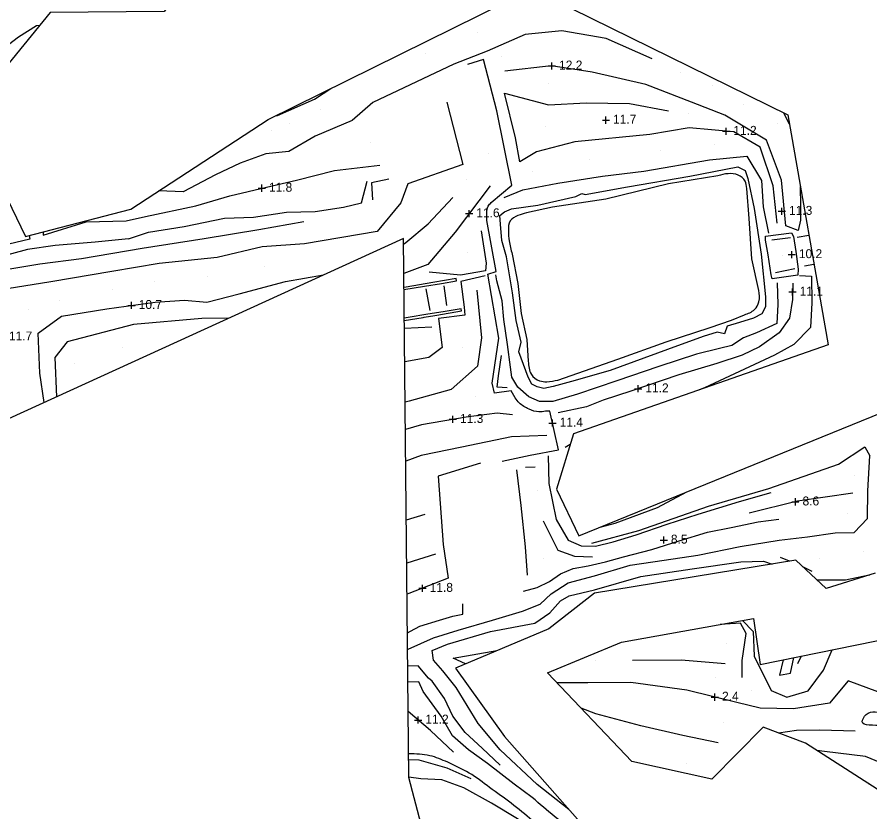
# Model space of a CAD drawing. Extents: x 2316231 to 2323598, y 363169 to 371906.
# Drawn here: x 2320880.2 to 2321357, y 369532.1 to 369976.5 of the extents above; entities that cross this region are included whole.
import ezdxf

# ---------------------------------------------------------------- set-up
doc = ezdxf.new("R2010")
doc.units = 0
for name, color, linetype in [('RD_DTM_BkLn1', 7, 'Continuous'), ('RD_DTM_Holes', 7, 'Continuous'), ('RD_DTM_Spot', 7, 'Continuous'), ('RD_DTM_TinHull', 7, 'Continuous'), ('RD_DTM_Void', 7, 'Continuous'), ('RD_EX_BldgApp', 7, 'Continuous'), ('RD_EX_H2O', 7, 'Continuous'), ('RD_EX_Road', 7, 'Continuous')]:
    doc.layers.add(name, color=color, linetype=linetype)

msp = doc.modelspace()

# ---------------------------------------------------------------- linework, layer by layer
at = {"layer": 'RD_DTM_BkLn1'}
for p, q in [((2321308.763, 369922.978), (2321311.938, 369916.742)), ((2321312.663, 369853.017), (2321302.145, 369851.663)), ((2321322.916, 369854.266), (2321316.329, 369853.314)), ((2321315.13, 369835.66), (2321304.272, 369833.408)), ((2321325.758, 369838.09), (2321320.399, 369837.22)), ((2321120.499, 369815.164), (2321119.001, 369826.233)), ((2321111.166, 369812.365), (2321109.01, 369824.539)), ((2321112.054, 369803.166), (2321096.729, 369802.277)), ((2321189.428, 369737.419), (2321186.709, 369735.907)), ((2321169.929, 369724.893), (2321164.543, 369724.581)), ((2321108.152, 369698.325), (2321097.812, 369695.229)), ((2321114.104, 369676.116), (2321098.056, 369671.125)), ((2321312.118, 369672.265), (2321306.975, 369674.295)), ((2321324.665, 369666.464), (2321319.862, 369668.929)), ((2321318.571, 369619.232), (2321316.569, 369614.883)), ((2321356.472, 369547.716), (2321356.759, 369547.802))]:
    msp.add_line(p, q, dxfattribs=at)
for points in [[(2320892.805, 369971.78), (2320891.11, 369971.664), (2320881.063, 369965.204), (2320869.634, 369956.682)], [(2321235.278, 369953.103), (2321209.567, 369964.402), (2321184.688, 369968.693), (2321164.253, 369966.7), (2321143.04, 369957.439), (2321124.355, 369950.144), (2321079.106, 369928.678), (2321067.49, 369918.696), (2321046.854, 369909.915), (2321032.108, 369901.364), (2321019.376, 369899.987), (2321004.974, 369894.795), (2320991.093, 369888.286), (2320972.982, 369878.763), (2320959.429, 369879.291)], [(2321318.087, 369881.749), (2321318.258, 369870.999), (2321318.219, 369862.984), (2321316.921, 369857.224), (2321310.009, 369859.798), (2321307.636, 369885.215), (2321299.19, 369907.738), (2321275.988, 369921.576), (2321257.216, 369928.974), (2321231.814, 369938.855), (2321201.776, 369945.722), (2321178.793, 369949.206), (2321152.99, 369946.161)], [(2321025.194, 369921.484), (2321025.821, 369921.483), (2321046.504, 369930.646), (2321055.7, 369936.567)], [(2321305.137, 369861.226), (2321302.843, 369882.113), (2321295.687, 369903.821), (2321280.9, 369912.222), (2321256.056, 369914.523), (2321234.016, 369910.864), (2321192.066, 369906.66), (2321170.523, 369901.133), (2321161.278, 369895.512), (2321158.825, 369908.935), (2321152.729, 369933.853), (2321177.316, 369927.405), (2321198.467, 369928.55), (2321222.522, 369928.22), (2321244.422, 369924.056)], [(2321120.408, 369928.849), (2321129.401, 369894.07), (2321098.761, 369883.201), (2321094.731, 369872.71)], [(2321152.582, 369875.657), (2321162.911, 369879.923), (2321182.624, 369883.661), (2321207.419, 369887.476), (2321230.646, 369890.32), (2321267.402, 369896.628), (2321288.276, 369898.764), (2321296.338, 369885.033), (2321297.413, 369870.403), (2321300.355, 369855.663)], [(2320894.758, 369856.403), (2320894.849, 369854.466), (2320918.785, 369862.073), (2320941.225, 369862.605), (2320951.927, 369864.981), (2320980.071, 369870.949), (2320999.175, 369876.601), (2321019.624, 369881.437), (2321036.347, 369885.279), (2321057.631, 369890.606), (2321073.456, 369892.508), (2321082.984, 369893.755)], [(2321180.005, 369769.933), (2321174.649, 369768.734), (2321171.023, 369769.774), (2321168.073, 369771.216), (2321165.866, 369775.105), (2321160.775, 369789.339), (2321162.049, 369794.762), (2321159.309, 369806.928), (2321157.157, 369822.283), (2321153.803, 369842.354), (2321151.172, 369851.494), (2321150.531, 369860.715), (2321150.116, 369865.529), (2321152.734, 369867.674), (2321156.721, 369869.206), (2321171.346, 369871.406), (2321192.536, 369876.16), (2321195.973, 369877.897), (2321197.881, 369877.27), (2321221.441, 369881.517), (2321256.387, 369887.554), (2321283.143, 369892.685), (2321287.248, 369890.754), (2321288.767, 369886.284), (2321292.35, 369869.36), (2321296.285, 369843.98), (2321298.71, 369820.091), (2321298.559, 369814.471), (2321296.629, 369810.58), (2321291.874, 369808.186), (2321284.094, 369805.706), (2321277.16, 369803.716), (2321275.801, 369799.394), (2321271.646, 369800.314), (2321263.856, 369797.957), (2321243.811, 369790.623), (2321211.884, 369778.885), (2321190.124, 369772.65), (2321180.005, 369769.933)], [(2320942.446, 369852.459), (2320953.74, 369856.272), (2320973.596, 369859.379), (2320996.124, 369863.992), (2321012.415, 369864.61), (2321030.832, 369867.477), (2321046.796, 369867.805), (2321062.725, 369870.133), (2321072.775, 369872.547), (2321075.937, 369884.717)], [(2321144.654, 369882.136), (2321125.126, 369856.151), (2321109.93, 369838.17), (2321096.416, 369833.187)], [(2321096.251, 369849.506), (2321097.579, 369850.36), (2321110.052, 369860.889), (2321123.815, 369875.605)], [(2321094.731, 369872.71), (2321081.602, 369856.653), (2321040.987, 369849.745), (2321017.27, 369847.96), (2320992.027, 369842.091), (2320959.557, 369838.696), (2320933.275, 369834.304), (2320899.096, 369828.432), (2320865.244, 369823.009)], [(2321139.766, 369856.9), (2321142.556, 369838.833), (2321142.019, 369834.676), (2321128.18, 369832.102), (2321110.528, 369833.806)], [(2320886.875, 369854.365), (2320887.419, 369852.354), (2320859.79, 369845.8), (2320822.868, 369837.839), (2320784.046, 369829.81), (2320747.027, 369824.896), (2320720.871, 369820.74), (2320695.484, 369812.994), (2320671.745, 369804.329), (2320650.55, 369791.718), (2320627.167, 369777.678), (2320602.537, 369763.622), (2320584.839, 369755.805), (2320564.208, 369750.61), (2320546.635, 369747.749), (2320525.628, 369748.402), (2320513.364, 369750.676)], [(2320895.341, 369761.015), (2320892.845, 369777.326), (2320891.909, 369799.824), (2320905.096, 369809.349), (2320930.319, 369813.375), (2320957.417, 369817.089), (2320973.891, 369818.212), (2320986.207, 369817.152), (2321004.406, 369821.673), (2321030.363, 369828.652), (2321051.573, 369832.274)], [(2321141.848, 369831.811), (2321128.242, 369828.662), (2321130.162, 369814.241), (2321130.601, 369809.787), (2321115.788, 369808.038), (2321117.946, 369791.828), (2321110.455, 369786.21), (2321096.916, 369783.789)], [(2321305.144, 369827.907), (2321305.602, 369815.741), (2321304.989, 369805.177), (2321293.677, 369799.904), (2321286.436, 369797.218), (2321279.805, 369792.832), (2321272.996, 369791.19), (2321260.008, 369787.926), (2321238.942, 369781.193), (2321215.577, 369773.055), (2321193.587, 369765.674), (2321179.695, 369761.537), (2321172.32, 369761.494), (2321166.241, 369764.188), (2321160.219, 369769.635), (2321156.874, 369775.239), (2321156.057, 369780.762), (2321154.399, 369793.406), (2321152.397, 369807.321), (2321151.436, 369817.78), (2321148.354, 369829.036), (2321147.831, 369832.321)], [(2321317.687, 369832.005), (2321324.272, 369831.558), (2321324.459, 369816.797), (2321323.718, 369802.861), (2321314.499, 369793.418), (2321303.757, 369787.478), (2321284.085, 369778.299), (2321264.481, 369769.176), (2321260.635, 369767.726)], [(2321313.866, 369827.685), (2321313.665, 369818.569), (2321312.108, 369808.156), (2321306.313, 369799.876), (2321295.225, 369792.106), (2321285.681, 369787.509), (2321271.471, 369782.722), (2321250.15, 369776.451), (2321223.362, 369767.262), (2321207.802, 369762.222), (2321198.611, 369758.478), (2321182.654, 369755.194)], [(2321137.167, 369823.841), (2321139.859, 369797.073), (2321137.647, 369781.368), (2321122.857, 369768.287), (2321099.488, 369761.712), (2321097.144, 369761.255)], [(2320998.773, 369808.191), (2320983.588, 369807.89), (2320945.273, 369804.681), (2320908.286, 369794.911), (2320901.375, 369786.131), (2320902.274, 369764.177)], [(2321154.181, 369769.271), (2321148.55, 369769.523), (2321149.357, 369775.95), (2321151.109, 369787.205)], [(2321157.232, 369754.092), (2321148.671, 369755.111), (2321131.202, 369752.858), (2321106.327, 369748.549), (2321097.299, 369745.877)], [(2321176.466, 369742.454), (2321156.712, 369741.852), (2321128.839, 369735.939), (2321106.198, 369731.271), (2321097.478, 369728.181)], [(2321201.536, 369682.393), (2321227.886, 369689.427), (2321266.802, 369702.953), (2321300.575, 369712.929), (2321339.367, 369726.546), (2321354.264, 369736.288), (2321356.904, 369731.149)], [(2321098.543, 369622.938), (2321098.874, 369623.097), (2321112.934, 369629.414), (2321126.736, 369633.731), (2321145.986, 369639.315), (2321162.794, 369644.281), (2321172.672, 369648.337), (2321178.86, 369654.073), (2321188.4, 369660.12), (2321203.055, 369664.13), (2321222.947, 369669.992), (2321241.925, 369672.856), (2321260.724, 369675.733), (2321284.455, 369680.396), (2321306.258, 369683.978), (2321322.072, 369685.857), (2321337.597, 369688.188), (2321348.231, 369688.249), (2321355.723, 369696.194), (2321355.865, 369711.639), (2321356.904, 369731.149)], [(2321139.329, 369727.12), (2321115.709, 369719.849), (2321118.514, 369681.547), (2321121.29, 369662.806), (2321099.282, 369654.121), (2321098.231, 369653.767)], [(2321159.444, 369723.302), (2321161.854, 369703.371), (2321164.193, 369680.303), (2321165.432, 369664.436)], [(2321254.451, 369710.913), (2321238.02, 369702.035), (2321214.348, 369693.292), (2321205.995, 369691.196)], [(2321347.551, 369710.251), (2321316.615, 369705.747), (2321289.525, 369699.066)], [(2321174.414, 369694.766), (2321182.508, 369678.517), (2321191.879, 369675.167), (2321201.87, 369674.691)], [(2321188.776, 369533.533), (2321171.026, 369547.442), (2321150.256, 369566.776), (2321137.972, 369581.461), (2321125.75, 369601.709), (2321118.263, 369610.952), (2321113.03, 369616.846), (2321112.27, 369622.346), (2321120.875, 369625.823), (2321144.921, 369632.924), (2321169.743, 369637.683), (2321178.101, 369643.488), (2321184.079, 369650.035), (2321188.826, 369652.901), (2321202.95, 369656.329), (2321228.908, 369663.668), (2321257.607, 369668.059), (2321284.762, 369671.952), (2321297.523, 369672.317), (2321302.388, 369670.679)], [(2321327.36, 369661.883), (2321343.427, 369661.911), (2321356.683, 369664.612), (2321356.977, 369664.645)], [(2321285.607, 369607.197), (2321285.687, 369616.842), (2321287.749, 369631.839), (2321284.743, 369637.7), (2321273.343, 369636.885)], [(2321285.792, 369639.119), (2321291.689, 369632.888), (2321292.297, 369619.137), (2321301.849, 369600.003), (2321310.611, 369596.228), (2321322.543, 369599.712), (2321331.098, 369611.384), (2321335.944, 369622.75)], [(2321374.115, 369630.481), (2321374.684, 369621.268), (2321375.241, 369603.83), (2321375.13, 369594.95), (2321361.481, 369599.209), (2321344.942, 369605.471), (2321334.416, 369592.977), (2321314.289, 369589.747), (2321295.664, 369590.084), (2321282.56, 369593.25), (2321254.648, 369600.209), (2321223.271, 369604.509), (2321199.337, 369604.175), (2321182.216, 369604.191)], [(2321130.974, 369614.856), (2321123.963, 369618.108), (2321148.502, 369622.263)], [(2321276.044, 369614.955), (2321251.424, 369617.008), (2321224.286, 369616.667)], [(2321308.542, 369617.2), (2321306.488, 369608.49), (2321312.621, 369609.742), (2321314.482, 369618.403)], [(2321150.304, 369558.255), (2321140.233, 369567.724), (2321130.776, 369576.414), (2321123.851, 369585.688), (2321119.121, 369595.581), (2321112.288, 369605.181), (2321110.251, 369606.933), (2321104.393, 369613.729), (2321098.638, 369613.526)], [(2321124.203, 369565.508), (2321111.334, 369577.633), (2321098.894, 369588.267)], [(2321272.266, 369570.694), (2321252.434, 369574.747), (2321228.92, 369580.166), (2321203.818, 369586.999), (2321195.602, 369590.064)], [(2321305.923, 369576.268), (2321316.03, 369577.879), (2321328.969, 369577.906), (2321348.741, 369577.507)], [(2321369.856, 369539.151), (2321377.63, 369544.643), (2321374.947, 369554.672), (2321354.505, 369563.079), (2321331.643, 369565.842), (2321327.253, 369566.414)], [(2321134.068, 369550.532), (2321120.753, 369556.476), (2321105.026, 369561.071), (2321099.168, 369561.218)], [(2321217.875, 369448.547), (2321215.847, 369459.508), (2321210.882, 369471.841), (2321205.697, 369482.782), (2321199.341, 369493.514), (2321190.845, 369503.381), (2321182.542, 369511.144), (2321171.084, 369519.967), (2321159.939, 369528.261), (2321145.39, 369536.987), (2321129.94, 369545.482), (2321117.732, 369550.083), (2321105.863, 369550.522), (2321099.266, 369551.456)]]:
    msp.add_lwpolyline(points, dxfattribs=at)
at = {"layer": 'RD_DTM_Holes'}
for points in [[(2321124.606, 370283.08), (2321175.43, 370167.171), (2321165.892, 370142.913), (2321102.435, 370077.997), (2320995.795, 370021.474), (2320962.442, 369979.593), (2320898.768, 369979.08), (2320851.962, 369921.773), (2320884.841, 369853.84), (2320943.763, 369869.068), (2321020.605, 369919.215), (2321168.221, 369992.199), (2321311.04, 369921.856), (2321333.631, 369793.28), (2321191.287, 369743.45), (2321181.751, 369712.515), (2321194.283, 369686.43), (2321363.394, 369755.241)], [(2321359.948, 369665.563), (2321332.477, 369657.074), (2321315.692, 369672.848), (2321203.009, 369654.474), (2321177.484, 369634.509), (2321125.273, 369612.447), (2321152.776, 369574.284), (2321218.918, 369499.411)], [(2321413.665, 369511.116), (2321320.952, 369570.447), (2321297.411, 369579.565), (2321268.627, 369550.398), (2321223.822, 369560.282), (2321176.781, 369609.927), (2321218.108, 369626.972), (2321291.848, 369640.206), (2321295.602, 369614.58), (2321381.74, 369632.025)]]:
    msp.add_lwpolyline(points, dxfattribs=at)
at = {"layer": 'RD_DTM_Spot'}
for p, q in [((2321137.379, 369967.595), (2321137.379, 369967.595)), ((2321108.523, 369956.28), (2321108.523, 369956.28)), ((2321150.905, 369954.175), (2321150.905, 369954.175)), ((2321250.866, 369945.485), (2321250.866, 369945.485)), ((2321177.531, 369939.241), (2321177.531, 369939.241)), ((2321268.761, 369938.114), (2321268.761, 369938.114)), ((2321286.315, 369927.833), (2321286.315, 369927.833)), ((2321049.804, 369924.908), (2321049.804, 369924.908)), ((2321255.644, 369922.361), (2321255.644, 369922.361)), ((2321032.757, 369916.975), (2321032.757, 369916.975)), ((2321209.425, 369918.875), (2321209.425, 369918.875)), ((2321305.407, 369917.016), (2321305.407, 369917.016)), ((2321022.385, 369913.057), (2321022.385, 369913.057)), ((2321175.774, 369915.373), (2321175.774, 369915.373)), ((2321005.29, 369909.07), (2321005.29, 369909.07)), ((2321077.681, 369906.078), (2321077.681, 369906.078)), ((2321270.198, 369905.169), (2321270.198, 369905.169)), ((2321143.988, 369900.058), (2321143.988, 369900.058)), ((2321240.044, 369901.932), (2321240.044, 369901.932)), ((2321200.202, 369896.841), (2321200.202, 369896.841)), ((2321168.615, 369890.182), (2321168.615, 369890.182)), ((2321131.328, 369885.697), (2321131.328, 369885.697)), ((2321321.565, 369845.825), (2321321.565, 369845.825)), ((2321132.209, 369844.807), (2321132.209, 369844.807)), ((2321308.411, 369843.191), (2321308.411, 369843.191)), ((2321018.533, 369837.185), (2321018.533, 369837.185)), ((2320986.85, 369831.605), (2320986.85, 369831.605)), ((2320956.776, 369828.547), (2320956.776, 369828.547)), ((2320933.822, 369824.218), (2320933.822, 369824.218)), ((2320903.912, 369817.955), (2320903.912, 369817.955)), ((2321318.544, 369820.985), (2321318.544, 369820.985)), ((2320886.318, 369812.981), (2320886.318, 369812.981)), ((2320938.995, 369791.963), (2320938.995, 369791.963)), ((2321129.119, 369791.493), (2321129.119, 369791.493)), ((2320912.218, 369782.706), (2320912.218, 369782.706)), ((2321136.374, 369764.49), (2321136.374, 369764.49)), ((2321348.25, 369719.938), (2321348.25, 369719.938)), ((2321171.406, 369711.89), (2321171.406, 369711.89)), ((2321344.597, 369699.159), (2321344.597, 369699.159)), ((2321174.335, 369673.779), (2321174.335, 369673.779)), ((2321328.692, 369673.853), (2321328.692, 369673.853)), ((2321353.688, 369677.588), (2321353.688, 369677.588)), ((2321277.099, 369626.304), (2321277.099, 369626.304)), ((2321203.805, 369616.924), (2321203.805, 369616.924)), ((2321270.837, 369607.46), (2321270.837, 369607.46)), ((2321291.012, 369599.763), (2321291.012, 369599.763)), ((2321274.907, 369582.057), (2321274.907, 369582.057)), ((2321254.269, 369559.157), (2321254.269, 369559.157))]:
    msp.add_line(p, q, dxfattribs=at)
at = {"layer": 'RD_DTM_TinHull'}
msp.add_lwpolyline([(2321400.963, 368599.408), (2321534.916, 368777.939), (2321271.463, 369044.178), (2321175.279, 369261.496), (2321099.267, 369551.406), (2321096.219, 369852.637), (2320858.06, 369744.011), (2320482.587, 369669.607), (2320232.924, 369604.892), (2319951.333, 369602.051), (2320092.085, 369259.27), (2319866.523, 369058.699), (2319771.694, 369171.639), (2319557.442, 369523.873), (2318254.179, 368711.432)], dxfattribs=at)
at = {"layer": 'RD_DTM_Void'}
for p, q in [((2321179.239, 369947.138), (2321179.239, 369951.138)), ((2321177.239, 369949.138), (2321181.239, 369949.138)), ((2321207.425, 369918.875), (2321211.425, 369918.875)), ((2321209.425, 369916.875), (2321209.425, 369920.875)), ((2321274.687, 369912.612), (2321278.687, 369912.612)), ((2321276.687, 369910.612), (2321276.687, 369914.612)), ((2321015.026, 369880.823), (2321019.026, 369880.823)), ((2321017.026, 369878.823), (2321017.026, 369882.823)), ((2321307.8, 369865.902), (2321307.8, 369869.902)), ((2321130.952, 369866.564), (2321134.952, 369866.564)), ((2321132.952, 369864.564), (2321132.952, 369868.564)), ((2321305.8, 369867.902), (2321309.8, 369867.902)), ((2321313.314, 369841.684), (2321313.314, 369845.684)), ((2321311.314, 369843.684), (2321315.314, 369843.684)), ((2321311.758, 369822.773), (2321315.758, 369822.773)), ((2321313.758, 369820.773), (2321313.758, 369824.773)), ((2320944.214, 369813.279), (2320944.214, 369817.279)), ((2320942.214, 369815.279), (2320946.214, 369815.279)), ((2321227.485, 369766.676), (2321227.485, 369770.676)), ((2321225.485, 369768.676), (2321229.485, 369768.676)), ((2321121.864, 369751.586), (2321125.864, 369751.586)), ((2321123.864, 369749.586), (2321123.864, 369753.586)), ((2321179.583, 369747.508), (2321179.583, 369751.508)), ((2321177.583, 369749.508), (2321181.583, 369749.508)), ((2321315.351, 369703.435), (2321315.351, 369707.435)), ((2321313.351, 369705.435), (2321317.351, 369705.435)), ((2321239.766, 369684.11), (2321243.766, 369684.11)), ((2321241.766, 369682.11), (2321241.766, 369686.11)), ((2321106.888, 369655.123), (2321106.888, 369659.123)), ((2321104.888, 369657.123), (2321108.888, 369657.123)), ((2321270.348, 369594.295), (2321270.348, 369598.295)), ((2321268.348, 369596.295), (2321272.348, 369596.295)), ((2321102.49, 369583.483), (2321106.49, 369583.483)), ((2321104.49, 369581.483), (2321104.49, 369585.483))]:
    msp.add_line(p, q, dxfattribs=at)
at = {"layer": 'RD_EX_BldgApp'}
for points in [[(2321096.508, 369824.093), (2321108.073, 369826.032), (2321117.48, 369827.61), (2321125.976, 369829.035), (2321125.773, 369830.245), (2321112.741, 369828.059), (2321097.711, 369825.539), (2321096.495, 369825.335)], [(2321128.458, 369813.37), (2321118.355, 369811.693), (2321109.936, 369810.295), (2321098.928, 369808.467), (2321096.67, 369808.092)], [(2321096.682, 369806.85), (2321107.223, 369808.6), (2321107.778, 369808.692), (2321113.846, 369809.7), (2321114.867, 369809.869), (2321128.659, 369812.159), (2321128.458, 369813.37)]]:
    msp.add_lwpolyline(points, dxfattribs=at)
at = {"layer": 'RD_EX_H2O'}
msp.add_line((2321182.608, 369773.563), (2321216.108, 369785.137), dxfattribs=at)
for points in [[(2321271.979, 369887.759), (2321244.394, 369883.261), (2321209.347, 369874.719), (2321179.58, 369870.175), (2321164.962, 369867.019)], [(2321294.961, 369823.651), (2321290.966, 369841.353), (2321289.512, 369863.775), (2321288.167, 369880.689)], [(2320942.446, 369852.459), (2320923.822, 369850.683), (2320901.566, 369848.812), (2320886.019, 369846.493), (2320868.021, 369841.679)], [(2321156.97, 369843.957), (2321160.116, 369827.428), (2321161.969, 369810.692), (2321165.148, 369796.198), (2321166.022, 369784.008)], [(2321216.108, 369785.137), (2321243.033, 369794.832), (2321267.668, 369802.952), (2321279.627, 369807.076), (2321286.847, 369810.009)]]:
    msp.add_lwpolyline(points, dxfattribs=at)
for points in [[(2321288.167, 369880.689), (2321287.186, 369884.752), (2321283.413, 369888.086), (2321277.741, 369888.923), (2321271.979, 369887.759)], [(2321164.962, 369867.019), (2321160.267, 369865.491), (2321155.902, 369862.522), (2321154.898, 369857.187), (2321155.319, 369851.306), (2321156.97, 369843.957)], [(2321286.847, 369810.009), (2321292.504, 369812.927), (2321294.987, 369817.322), (2321294.961, 369823.651)], [(2321166.022, 369784.008), (2321167.729, 369776.726), (2321172.377, 369773.14), (2321176.297, 369772.593), (2321182.608, 369773.563)], [(2321388.387, 369527.292), (2321389.857, 369534.714), (2321394.447, 369544.753), (2321386.465, 369558.472), (2321376.513, 369569.492), (2321363.975, 369580.221), (2321352.745, 369582.512), (2321354.922, 369586.538), (2321365.858, 369586.102), (2321379.447, 369581.045), (2321384.427, 369592.6), (2321386.424, 369608.014), (2321386.449, 369622.492), (2321383.552, 369639.436), (2321382.405, 369647.232)]]:
    msp.add_spline(points, degree=3, dxfattribs=at)
at = {"layer": 'RD_EX_Road'}
for points in [[(2321145.306, 369872.713), (2321156.831, 369882.516), (2321148.376, 369924.082), (2321140.916, 369952.829), (2321132.123, 369950.028)], [(2321088.128, 369885.917), (2321078.451, 369883.817), (2321078.832, 369874.282)], [(2321040.54, 369861.944), (2321015.372, 369857.615), (2320984.804, 369852.524), (2320950.199, 369847.082), (2320916.155, 369841.334), (2320892.905, 369838.344), (2320854.731, 369831.941), (2320818.448, 369825.866), (2320782.324, 369820.061), (2320736.523, 369812.379)], [(2321158.672, 369763.64), (2321156.488, 369767.529), (2321147.072, 369766.203), (2321145.908, 369771.796), (2321149.559, 369796.903), (2321143.404, 369832.759), (2321148.087, 369834.152), (2321142.919, 369862.787)], [(2321316.631, 369832.157), (2321302.367, 369830.18), (2321301.85, 369832.453), (2321300.15, 369843.579), (2321298.66, 369851.669), (2321298.56, 369854.041), (2321313.114, 369855.769), (2321314.252, 369853.887), (2321315.593, 369845.337), (2321316.94, 369835.539), (2321316.631, 369832.157)], [(2321151.396, 369728.13), (2321167.161, 369731.46), (2321182.903, 369734.497), (2321178.117, 369756.138), (2321175.678, 369756.06)], [(2321177.176, 369731.175), (2321177.483, 369715.706), (2321181.568, 369695.586), (2321188.324, 369684.02), (2321195.627, 369680.826), (2321203.63, 369680.708), (2321213.399, 369683.089), (2321226.301, 369687.096), (2321243.596, 369692.937), (2321260.924, 369698.485), (2321284.06, 369705.646), (2321301.733, 369710.743)], [(2321163.32, 369655.52), (2321170.952, 369657.529), (2321177.938, 369661.003), (2321184.051, 369665.211), (2321191.136, 369668.111), (2321199.474, 369669.678), (2321209.219, 369671.857), (2321219.305, 369674.652), (2321235.142, 369678.791), (2321250.431, 369683.596), (2321266.283, 369688.499), (2321279.436, 369691.021), (2321294.538, 369694.365), (2321306.068, 369695.816)], [(2321098.45, 369632.179), (2321100.193, 369633.197), (2321105.377, 369635.926), (2321116.421, 369639.211), (2321123.851, 369641.468), (2321129.5, 369642.644), (2321129.371, 369648.4)], [(2321168.225, 369540.126), (2321158.065, 369547.56), (2321143.271, 369559.087), (2321132.595, 369566.772), (2321123.719, 369574.706), (2321117.229, 369585.54), (2321107.303, 369599.46), (2321104.89, 369604.879), (2321098.729, 369604.607)]]:
    msp.add_lwpolyline(points, dxfattribs=at)
for points in [[(2321142.919, 369862.787), (2321142.793, 369866.924), (2321143.655, 369870.787), (2321145.306, 369872.713)], [(2321175.678, 369756.06), (2321171.933, 369755.718), (2321166.421, 369757.285), (2321160.963, 369760.751), (2321158.672, 369763.64)], [(2321218.175, 369465.345), (2321212.37, 369477.421), (2321203.424, 369491.763), (2321191.559, 369504.591), (2321181.257, 369515.219), (2321168.231, 369527.266), (2321156.451, 369536.934), (2321144.409, 369545.749), (2321132.971, 369553.853), (2321120.949, 369559.836), (2321110.974, 369563.538), (2321099.134, 369564.566)], [(2321228.559, 369468.417), (2321225.004, 369479.44), (2321217.446, 369494.765), (2321206.433, 369507.217), (2321193.665, 369519.285), (2321180.764, 369529.532), (2321168.225, 369540.126)]]:
    msp.add_spline(points, degree=3, dxfattribs=at)

# ---------------------------------------------------------------- texts
at = {"layer": 'RD_DTM_Void'}
for s, p in [('12.2', (2321183.239, 369947.138)), ('11.7', (2321213.425, 369916.875)), ('11.2', (2321280.687, 369910.612)), ('11.8', (2321021.026, 369878.823)), ('11.6', (2321136.952, 369864.564)), ('11.3', (2321311.8, 369865.902)), ('10.2', (2321317.314, 369841.684)), ('11.1', (2321317.758, 369820.773)), ('10.7', (2320948.214, 369813.279)), ('11.7', (2320875.66, 369795.677)), ('11.2', (2321231.485, 369766.676)), ('11.3', (2321127.864, 369749.586)), ('11.4', (2321183.583, 369747.508)), ('8.6', (2321319.351, 369703.435)), ('8.5', (2321245.766, 369682.11)), ('11.8', (2321110.888, 369655.123)), ('2.4', (2321274.348, 369594.295)), ('11.2', (2321108.49, 369581.483))]:
    msp.add_text(s, height=5, dxfattribs=at).set_placement(p)

doc.saveas('drawing.dxf')
